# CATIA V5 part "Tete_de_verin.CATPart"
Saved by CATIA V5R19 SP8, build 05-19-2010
Part number: Tete
Revision: ANY
Definition: UNKNOWN
Nomenclature: Tete de vérin
Source: Unknown
Bounding box of the stored display mesh (mm): x -6.25 to 6.25, y -6.25 to 6.25, z -14.8 to 31.5
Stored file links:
  D:\Documents\1_Travail\1 - ac-limoges.fr\OneDrive - ac-limoges.fr\STI2D_Turgot\2 -2I2D\3_SEQUENCE_Serre_Connectée\3- Spécificités\ITEC\EC 3 Ouverture automatique\Simulation  Ouverture Automatique\Tete_de_verin.CATPart
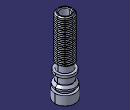
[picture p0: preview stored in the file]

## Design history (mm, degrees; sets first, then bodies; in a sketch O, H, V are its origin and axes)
Body1 "NONE" (main body)
  Solid1: solid without history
